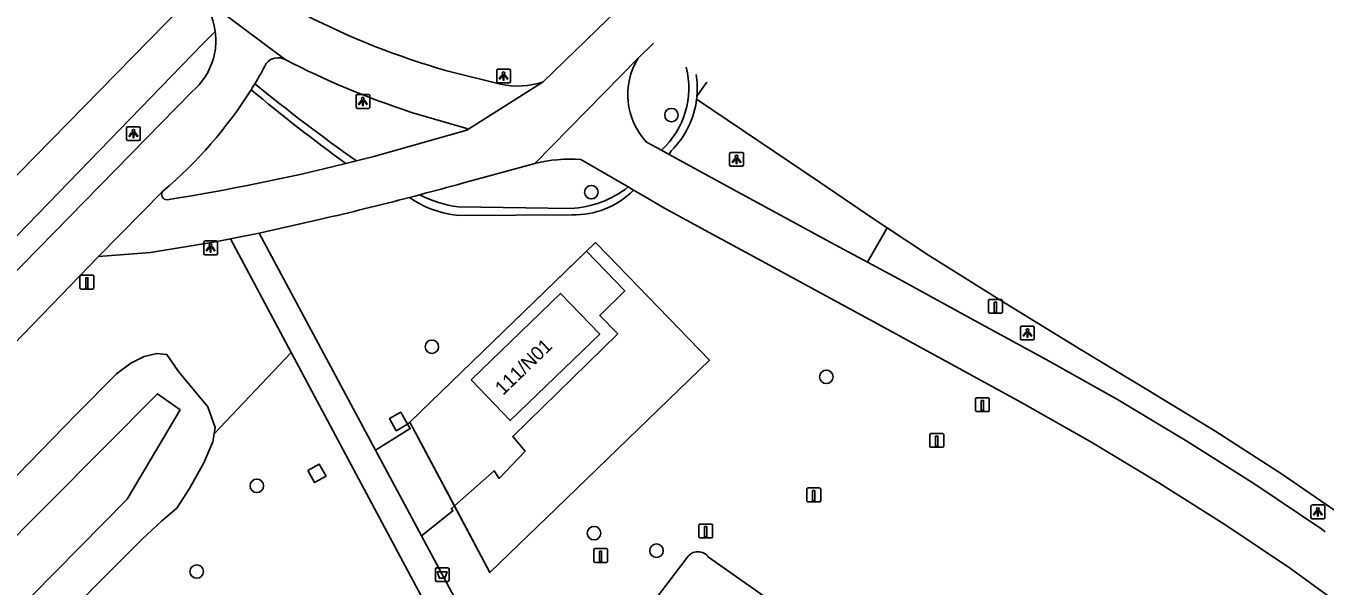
# Model space of a CAD drawing. Extents: x 155640 to 156810, y 382822 to 384046.
# Drawn here: x 156368.2 to 156462.3, y 383285.4 to 383326 of the extents above; entities that cross this region are included whole.
import ezdxf

# ---------------------------------------------------------------- set-up
doc = ezdxf.new("R2010")
doc.units = 0
for name, color, linetype in [('IMGEO_Afvalbak', 7, 'Continuous'), ('IMGEO_Berm_groen', 7, 'Continuous'), ('IMGEO_Boom', 7, 'Continuous'), ('IMGEO_Fietspad_gesloten', 7, 'Continuous'), ('IMGEO_Groenvoorziening', 7, 'Continuous'), ('IMGEO_Haag', 7, 'Continuous'), ('IMGEO_Hek', 7, 'Continuous'), ('IMGEO_Lichtpunt', 7, 'Continuous'), ('IMGEO_Muur', 7, 'Continuous'), ('IMGEO_Paal', 7, 'Continuous'), ('IMGEO_Pand', 7, 'Continuous'), ('IMGEO_Pand_nummerreeks', 7, 'Continuous'), ('IMGEO_Verkeerseiland_open', 7, 'Continuous'), ('IMGEO_Voetpad_gesloten', 7, 'Continuous'), ('IMGEO_Voetpad_onverhard', 7, 'Continuous'), ('IMGEO_Voetpad_open', 7, 'Continuous'), ('IMGEO_Waterloop', 7, 'Continuous')]:
    doc.layers.add(name, color=color, linetype=linetype)

msp = doc.modelspace()

# ---------------------------------------------------------------- linework, layer by layer
at = {"layer": 'IMGEO_Afvalbak'}
for p, q in [((156397.846, 383285.845), (156397.846, 383286.645)), ((156397.846, 383286.645), (156397.846, 383285.845)), ((156397.946, 383286.745), (156398.736, 383286.745)), ((156398.736, 383286.745), (156397.946, 383286.745)), ((156398.836, 383286.645), (156398.836, 383285.845)), ((156398.836, 383285.845), (156398.836, 383286.645)), ((156398.736, 383285.745), (156397.946, 383285.745)), ((156397.946, 383285.745), (156398.736, 383285.745))]:
    msp.add_line(p, q, dxfattribs=at)
msp.add_lwpolyline([(156397.989, 383286.459), (156398.693, 383286.459), (156398.544, 383285.989), (156398.138, 383285.989), (156397.989, 383286.459)], dxfattribs=at)
for centre, start, end in [((156397.946, 383286.645), 90, 180), ((156397.946, 383286.645), 90, 180), ((156398.736, 383286.645), 0, 90), ((156398.736, 383286.645), 360, 90), ((156397.946, 383285.845), 180, 270), ((156397.946, 383285.845), 180, 270), ((156398.736, 383285.845), 270, 0), ((156398.736, 383285.845), 270, 0)]:
    msp.add_arc(centre, 0.1, start, end, dxfattribs=at)
at = {"layer": 'IMGEO_Berm_groen'}
for points in [[(156387.41, 383302.346), (156383.014, 383310.578)], [(156233.027, 383113.173), (156252.866, 383146.34), (156268.602, 383172.647), (156299.809, 383224.819), (156307.157, 383232.786), (156316.472, 383242.07), (156333.801, 383259.79), (156347.065, 383272.962), (156352.588, 383278.703), (156361.434, 383287.344), (156366.724, 383292.604), (156371.834, 383297.853), (156374.748, 383300.784), (156375.78, 383301.56), (156376.759, 383302.039), (156377.674, 383302.264), (156378.399, 383302.193), (156379.248, 383300.961), (156381.369, 383298.415), (156381.897, 383296.903), (156381.815, 383296.443)], [(156387.41, 383302.346), (156381.815, 383296.443)]]:
    msp.add_lwpolyline(points, dxfattribs=at)
at = {"layer": 'IMGEO_Boom'}
for centre in [(156414.951, 383319.535), (156409.148, 383313.953), (156397.595, 383302.756), (156426.175, 383300.58), (156384.909, 383292.681), (156409.344, 383289.257), (156413.866, 383287.982), (156380.557, 383286.474)]:
    msp.add_circle(centre, 0.489, dxfattribs=at)
at = {"layer": 'IMGEO_Fietspad_gesloten'}
for points in [[(156386.96, 383323.552), (156380.504, 383328.406)], [(156411.874, 383327.981), (156405.667, 383321.95)], [(156413.66, 383324.737), (156412.539, 383323.648)], [(156405.049, 383316.037), (156412.539, 383323.648)], [(156402.557, 383321.777), (156398.667, 383322.745)], [(156405.667, 383321.95), (156400.124, 383318.442)], [(156380.194, 383321.217), (156360.181, 383300.803), (156343.328, 383283.312), (156320.142, 383258.454)], [(156384.5, 383321.375), (156384.634, 383321.592), (156384.768, 383321.81)], [(156396.11, 383319.733), (156400.129, 383318.562), (156400.124, 383318.442)], [(156400.124, 383318.442), (156393.394, 383316.534), (156392.135, 383316.212)], [(156413.154, 383317.575), (156414.222, 383316.991)], [(156392.135, 383316.212), (156391.748, 383316.116), (156391.361, 383316.02)], [(156408.386, 383316.322), (156411.813, 383314.329)], [(156414.222, 383316.991), (156414.359, 383316.916), (156414.78, 383316.686)], [(156414.78, 383316.686), (156419.216, 383314.26), (156426.506, 383310.311), (156429.166, 383308.873)], [(156399.819, 383314.599), (156405.049, 383316.037)], [(156411.813, 383314.329), (156412.207, 383314.099)], [(156373.432, 383309.293), (156378.108, 383314.02)], [(156395.984, 383313.573), (156396.356, 383313.67), (156396.729, 383313.767)], [(156469.029, 383279.65), (156464.349, 383283.389), (156459.799, 383286.696), (156455.125, 383289.825), (156450.27, 383292.91), (156445.339, 383295.87), (156440.217, 383298.767), (156435.055, 383301.593), (156429.889, 383304.414), (156427.301, 383305.816), (156421.201, 383309.128), (156417.685, 383311.033), (156414.393, 383312.827), (156412.93, 383313.678), (156412.207, 383314.099)], [(156385.084, 383310.986), (156389.538, 383311.991)], [(156383.014, 383310.578), (156381.78, 383310.334), (156377.211, 383309.584), (156373.432, 383309.293)], [(156383.014, 383310.578), (156385.084, 383310.986)], [(156373.432, 383309.293), (156346.778, 383281.729), (156322.635, 383255.833)], [(156462.324, 383289.355), (156462.066, 383289.543), (156457.215, 383292.799), (156452.282, 383295.927), (156447.27, 383298.926), (156442.11, 383301.833), (156436.911, 383304.669), (156431.712, 383307.496), (156429.166, 383308.873)]]:
    msp.add_lwpolyline(points, dxfattribs=at)
for centre, radius, start, end in [((156377.296, 383325.073), 4.626, 6.52779, 46.09498), ((156414.327, 383377.419), 56.872, 242.94269, 254.01676), ((156377.156, 383324.92), 4.785, 353.42613, 8.16143), ((156377.193, 383324.912), 4.747, 344.44891, 353.47288), ((156377.133, 383324.925), 4.808, 309.53884, 344.48996), ((156362.021, 383335.7), 26.653, 328.59089, 332.19886), ((156386.438, 383322.641), 1.05, 60.19021, 143.26914), ((156415.713, 383379.57), 62.966, 242.82975, 251.86117), ((156416.776, 383321.009), 4.992, 148.08972, 223.4753), ((156403.809, 383327.314), 5.676, 257.25954, 289.10828), ((156357.442, 383338.435), 31.988, 310.24597, 327.76827), ((156407.66, 383305.149), 11.196, 86.27976, 103.48336), ((156353.48, 383470.12), 158.687, 279.04397, 283.81086), ((156332.865, 383557.107), 251.581, 284.70542, 285.43422), ((156378.385, 383313.773), 0.371, 138.27225, 276.11786), ((156334.578, 383549.852), 244.128, 283.01029, 284.56809)]:
    msp.add_arc(centre, radius, start, end, dxfattribs=at)
at = {"layer": 'IMGEO_Groenvoorziening'}
for points in [[(156385.084, 383310.986), (156393.506, 383295.268)], [(156408.79, 383309.671), (156409.44, 383310.3), (156410.313, 383309.402), (156417.72, 383301.78), (156406.599, 383291.031), (156401.804, 383286.397), (156399.225, 383291.239)], [(156401.917, 383275.179), (156387.41, 383302.346)], [(156381.815, 383296.443), (156381.713, 383295.875), (156381.067, 383294.349), (156380.037, 383292.488), (156379.109, 383291.061), (156378.013, 383290.134), (156376.603, 383288.823), (156373.814, 383286.022), (156313.066, 383224.543), (156307.199, 383217.739), (156241.776, 383106.748)], [(156396.831, 383289.064), (156404.514, 383274.725)], [(156391.304, 383256.05), (156399.967, 383266.294), (156405.916, 383274.122), (156416.081, 383287.497)], [(156417.644, 383287.515), (156464.717, 383254.463), (156470.772, 383249.999), (156500, 383228.451), (156512.747, 383219.053)]]:
    msp.add_lwpolyline(points, dxfattribs=at)
msp.add_arc((156416.869, 383286.945), 0.962, 36.33381, 144.9858, dxfattribs=at)
at = {"layer": 'IMGEO_Haag'}
for points in [[(156414.78, 383316.686), (156414.939, 383316.944)], [(156429.166, 383308.873), (156430.583, 383311.361)]]:
    msp.add_lwpolyline(points, dxfattribs=at)
msp.add_arc((156410.444, 383321.475), 6.382, 314.77376, 352.81071, dxfattribs=at)
at = {"layer": 'IMGEO_Hek'}
for points in [[(156396, 383297.293), (156409.44, 383310.3)], [(156409.44, 383310.3), (156410.313, 383309.402)], [(156410.313, 383309.402), (156417.72, 383301.78), (156406.599, 383291.031)], [(156396, 383297.293), (156401.804, 383286.397)], [(156406.599, 383291.031), (156401.804, 383286.397)]]:
    msp.add_lwpolyline(points, dxfattribs=at)
at = {"layer": 'IMGEO_Lichtpunt'}
for p, q in [((156402.29, 383322.763), (156402.29, 383321.956)), ((156402.29, 383322.763), (156402.29, 383321.956)), ((156403.192, 383322.858), (156402.384, 383322.858)), ((156403.192, 383322.858), (156402.384, 383322.858)), ((156403.286, 383321.956), (156403.286, 383322.763)), ((156403.286, 383321.956), (156403.286, 383322.763)), ((156402.384, 383321.862), (156403.192, 383321.862)), ((156402.384, 383321.862), (156403.192, 383321.862)), ((156392.102, 383320.925), (156392.102, 383320.118)), ((156392.102, 383320.925), (156392.102, 383320.118)), ((156393.004, 383321.02), (156392.196, 383321.02)), ((156393.004, 383321.02), (156392.196, 383321.02)), ((156393.098, 383320.118), (156393.098, 383320.925)), ((156393.098, 383320.118), (156393.098, 383320.925)), ((156392.196, 383320.024), (156393.004, 383320.024)), ((156392.196, 383320.024), (156393.004, 383320.024)), ((156375.469, 383318.599), (156375.469, 383317.792)), ((156375.469, 383318.599), (156375.469, 383317.792)), ((156376.371, 383318.694), (156375.563, 383318.694)), ((156376.371, 383318.694), (156375.563, 383318.694)), ((156376.465, 383317.792), (156376.465, 383318.599)), ((156376.465, 383317.792), (156376.465, 383318.599)), ((156375.563, 383317.698), (156376.371, 383317.698)), ((156375.563, 383317.698), (156376.371, 383317.698)), ((156419.169, 383316.73), (156419.169, 383315.923)), ((156419.169, 383316.73), (156419.169, 383315.923)), ((156420.071, 383316.825), (156419.263, 383316.825)), ((156420.071, 383316.825), (156419.263, 383316.825)), ((156420.165, 383315.923), (156420.165, 383316.73)), ((156420.165, 383315.923), (156420.165, 383316.73)), ((156419.263, 383315.829), (156420.071, 383315.829)), ((156419.263, 383315.829), (156420.071, 383315.829)), ((156381.064, 383310.322), (156381.064, 383309.515)), ((156381.064, 383310.322), (156381.064, 383309.515)), ((156381.966, 383310.417), (156381.158, 383310.417)), ((156381.966, 383310.417), (156381.158, 383310.417)), ((156382.06, 383309.515), (156382.06, 383310.322)), ((156382.06, 383309.515), (156382.06, 383310.322)), ((156381.158, 383309.421), (156381.966, 383309.421)), ((156381.158, 383309.421), (156381.966, 383309.421)), ((156440.244, 383304.152), (156440.244, 383303.345)), ((156440.244, 383304.152), (156440.244, 383303.345)), ((156441.146, 383304.247), (156440.338, 383304.247)), ((156441.146, 383304.247), (156440.338, 383304.247)), ((156441.24, 383303.345), (156441.24, 383304.152)), ((156441.24, 383303.345), (156441.24, 383304.152)), ((156440.338, 383303.251), (156441.146, 383303.251)), ((156440.338, 383303.251), (156441.146, 383303.251)), ((156461.288, 383291.201), (156461.288, 383290.394)), ((156461.288, 383291.201), (156461.288, 383290.394)), ((156462.19, 383291.296), (156461.382, 383291.296)), ((156462.19, 383291.296), (156461.382, 383291.296)), ((156462.284, 383290.394), (156462.284, 383291.201)), ((156462.284, 383290.394), (156462.284, 383291.201)), ((156461.382, 383290.3), (156462.19, 383290.3)), ((156461.382, 383290.3), (156462.19, 383290.3))]:
    msp.add_line(p, q, dxfattribs=at)
for points in [[(156402.664, 383322.427), (156402.703, 383322.399), (156402.515, 383322.137), (156402.477, 383322.164), (156402.664, 383322.427)], [(156402.766, 383322.379), (156402.813, 383322.379), (156402.813, 383322.057), (156402.766, 383322.057), (156402.766, 383322.379)], [(156402.876, 383322.399), (156402.914, 383322.426), (156403.101, 383322.164), (156403.062, 383322.136), (156402.876, 383322.399)], [(156392.476, 383320.589), (156392.515, 383320.561), (156392.327, 383320.299), (156392.289, 383320.326), (156392.476, 383320.589)], [(156392.578, 383320.541), (156392.625, 383320.541), (156392.625, 383320.219), (156392.578, 383320.219), (156392.578, 383320.541)], [(156392.688, 383320.561), (156392.726, 383320.588), (156392.913, 383320.326), (156392.874, 383320.298), (156392.688, 383320.561)], [(156375.843, 383318.263), (156375.882, 383318.235), (156375.694, 383317.973), (156375.656, 383318), (156375.843, 383318.263)], [(156375.945, 383318.215), (156375.992, 383318.215), (156375.992, 383317.893), (156375.945, 383317.893), (156375.945, 383318.215)], [(156376.055, 383318.235), (156376.093, 383318.262), (156376.28, 383318), (156376.241, 383317.972), (156376.055, 383318.235)], [(156419.543, 383316.394), (156419.582, 383316.366), (156419.394, 383316.104), (156419.356, 383316.131), (156419.543, 383316.394)], [(156419.645, 383316.346), (156419.692, 383316.346), (156419.692, 383316.024), (156419.645, 383316.024), (156419.645, 383316.346)], [(156419.755, 383316.366), (156419.793, 383316.393), (156419.98, 383316.131), (156419.941, 383316.103), (156419.755, 383316.366)], [(156381.438, 383309.986), (156381.477, 383309.958), (156381.289, 383309.696), (156381.251, 383309.723), (156381.438, 383309.986)], [(156381.54, 383309.938), (156381.587, 383309.938), (156381.587, 383309.616), (156381.54, 383309.616), (156381.54, 383309.938)], [(156381.65, 383309.958), (156381.688, 383309.985), (156381.875, 383309.723), (156381.836, 383309.695), (156381.65, 383309.958)], [(156440.618, 383303.816), (156440.657, 383303.788), (156440.469, 383303.526), (156440.431, 383303.553), (156440.618, 383303.816)], [(156440.72, 383303.768), (156440.767, 383303.768), (156440.767, 383303.446), (156440.72, 383303.446), (156440.72, 383303.768)], [(156440.83, 383303.788), (156440.868, 383303.815), (156441.055, 383303.553), (156441.016, 383303.525), (156440.83, 383303.788)], [(156461.662, 383290.865), (156461.701, 383290.837), (156461.513, 383290.575), (156461.475, 383290.602), (156461.662, 383290.865)], [(156461.764, 383290.817), (156461.811, 383290.817), (156461.811, 383290.495), (156461.764, 383290.495), (156461.764, 383290.817)], [(156461.874, 383290.837), (156461.912, 383290.864), (156462.099, 383290.602), (156462.06, 383290.574), (156461.874, 383290.837)]]:
    msp.add_lwpolyline(points, dxfattribs=at)
for centre in [(156402.789, 383322.561), (156392.601, 383320.723), (156375.968, 383318.397), (156419.668, 383316.528), (156381.563, 383310.12), (156440.743, 383303.95), (156461.787, 383290.999)]:
    msp.add_circle(centre, 0.0994, dxfattribs=at)
for centre, start, end in [((156402.384, 383322.763), 90, 180), ((156402.384, 383322.763), 90, 180), ((156403.192, 383322.763), 0, 90), ((156403.192, 383322.763), 0, 90), ((156402.384, 383321.956), 180, 270), ((156402.384, 383321.956), 180, 270), ((156403.192, 383321.956), 270, 0), ((156403.192, 383321.956), 270, 360), ((156392.196, 383320.925), 90, 180), ((156392.196, 383320.925), 90, 180), ((156393.004, 383320.925), 0, 90), ((156393.004, 383320.925), 0, 90), ((156392.196, 383320.118), 180, 270), ((156392.196, 383320.118), 180, 270), ((156393.004, 383320.118), 270, 0), ((156393.004, 383320.118), 270, 360), ((156375.563, 383318.599), 90, 180), ((156375.563, 383318.599), 90, 180), ((156376.371, 383318.599), 0, 90), ((156376.371, 383318.599), 0, 90), ((156375.563, 383317.792), 180, 270), ((156375.563, 383317.792), 180, 270), ((156376.371, 383317.792), 270, 0), ((156376.371, 383317.792), 270, 360), ((156419.263, 383316.73), 90, 180), ((156419.263, 383316.73), 90, 180), ((156420.071, 383316.73), 0, 90), ((156420.071, 383316.73), 0, 90), ((156419.263, 383315.923), 180, 270), ((156419.263, 383315.923), 180, 270), ((156420.071, 383315.923), 270, 0), ((156420.071, 383315.923), 270, 360), ((156381.158, 383310.322), 90, 180), ((156381.158, 383310.322), 90, 180), ((156381.966, 383310.322), 0, 90), ((156381.966, 383310.322), 0, 90), ((156381.158, 383309.515), 180, 270), ((156381.158, 383309.515), 180, 270), ((156381.966, 383309.515), 270, 0), ((156381.966, 383309.515), 270, 360), ((156440.338, 383304.152), 90, 180), ((156440.338, 383304.152), 90, 180), ((156441.146, 383304.152), 0, 90), ((156441.146, 383304.152), 0, 90), ((156440.338, 383303.345), 180, 270), ((156440.338, 383303.345), 180, 270), ((156441.146, 383303.345), 270, 0), ((156441.146, 383303.345), 270, 360), ((156461.382, 383291.201), 90, 180), ((156461.382, 383291.201), 90, 180), ((156462.19, 383291.201), 0, 90), ((156462.19, 383291.201), 0, 90), ((156461.382, 383290.394), 180, 270), ((156461.382, 383290.394), 180, 270), ((156462.19, 383290.394), 270, 0), ((156462.19, 383290.394), 270, 360)]:
    msp.add_arc(centre, 0.0946, start, end, dxfattribs=at)
at = {"layer": 'IMGEO_Muur'}
for points in [[(156395.84, 383297.138), (156395.016, 383296.673), (156394.52, 383297.548), (156395.342, 383298.015), (156395.84, 383297.138)], [(156388.605, 383293.791), (156389.427, 383294.258), (156389.924, 383293.383), (156389.101, 383292.916), (156388.605, 383293.791)]]:
    msp.add_lwpolyline(points, dxfattribs=at)
at = {"layer": 'IMGEO_Paal'}
for p, q in [((156372.099, 383307.854), (156372.099, 383307.013)), ((156372.099, 383307.854), (156372.099, 383307.013)), ((156373.015, 383307.938), (156372.174, 383307.938)), ((156373.015, 383307.938), (156372.174, 383307.938)), ((156373.099, 383307.022), (156373.099, 383307.863)), ((156373.099, 383307.022), (156373.099, 383307.863)), ((156372.183, 383306.938), (156373.024, 383306.938)), ((156372.183, 383306.938), (156373.024, 383306.938)), ((156437.927, 383306.098), (156437.927, 383305.257)), ((156437.927, 383306.098), (156437.927, 383305.257)), ((156438.843, 383306.182), (156438.002, 383306.182)), ((156438.843, 383306.182), (156438.002, 383306.182)), ((156438.927, 383305.266), (156438.927, 383306.107)), ((156438.927, 383305.266), (156438.927, 383306.107)), ((156438.011, 383305.182), (156438.852, 383305.182)), ((156438.011, 383305.182), (156438.852, 383305.182)), ((156436.98, 383298.976), (156436.98, 383298.135)), ((156436.98, 383298.976), (156436.98, 383298.135)), ((156437.896, 383299.06), (156437.055, 383299.06)), ((156437.896, 383299.06), (156437.055, 383299.06)), ((156437.98, 383298.144), (156437.98, 383298.985)), ((156437.98, 383298.144), (156437.98, 383298.985)), ((156437.064, 383298.06), (156437.905, 383298.06)), ((156437.064, 383298.06), (156437.905, 383298.06)), ((156434.591, 383296.475), (156433.75, 383296.475)), ((156434.591, 383296.475), (156433.75, 383296.475)), ((156433.675, 383296.391), (156433.675, 383295.55)), ((156433.675, 383296.391), (156433.675, 383295.55)), ((156433.759, 383295.475), (156434.6, 383295.475)), ((156433.759, 383295.475), (156434.6, 383295.475)), ((156434.675, 383295.559), (156434.675, 383296.4)), ((156434.675, 383295.559), (156434.675, 383296.4)), ((156424.763, 383292.443), (156424.763, 383291.602)), ((156424.763, 383292.443), (156424.763, 383291.602)), ((156425.679, 383292.527), (156424.838, 383292.527)), ((156425.679, 383292.527), (156424.838, 383292.527)), ((156425.763, 383291.611), (156425.763, 383292.452)), ((156425.763, 383291.611), (156425.763, 383292.452)), ((156424.847, 383291.527), (156425.688, 383291.527)), ((156424.847, 383291.527), (156425.688, 383291.527)), ((156416.935, 383289.833), (156416.935, 383288.992)), ((156416.935, 383289.833), (156416.935, 383288.992)), ((156417.851, 383289.917), (156417.01, 383289.917)), ((156417.851, 383289.917), (156417.01, 383289.917)), ((156417.935, 383289.001), (156417.935, 383289.842)), ((156417.935, 383289.001), (156417.935, 383289.842)), ((156417.019, 383288.917), (156417.86, 383288.917)), ((156417.019, 383288.917), (156417.86, 383288.917)), ((156409.319, 383288.05), (156409.319, 383287.209)), ((156409.319, 383288.05), (156409.319, 383287.209)), ((156410.235, 383288.134), (156409.394, 383288.134)), ((156410.235, 383288.134), (156409.394, 383288.134)), ((156410.319, 383287.218), (156410.319, 383288.059)), ((156410.319, 383287.218), (156410.319, 383288.059)), ((156409.403, 383287.134), (156410.244, 383287.134)), ((156409.403, 383287.134), (156410.244, 383287.134))]:
    msp.add_line(p, q, dxfattribs=at)
for points in [[(156372.514, 383307.751), (156372.674, 383307.751), (156372.674, 383307.018), (156372.514, 383307.018), (156372.514, 383307.751)], [(156438.342, 383305.995), (156438.502, 383305.995), (156438.502, 383305.262), (156438.342, 383305.262), (156438.342, 383305.995)], [(156437.395, 383298.873), (156437.555, 383298.873), (156437.555, 383298.14), (156437.395, 383298.14), (156437.395, 383298.873)], [(156434.09, 383296.288), (156434.25, 383296.288), (156434.25, 383295.555), (156434.09, 383295.555), (156434.09, 383296.288)], [(156425.178, 383292.34), (156425.338, 383292.34), (156425.338, 383291.607), (156425.178, 383291.607), (156425.178, 383292.34)], [(156417.35, 383289.73), (156417.51, 383289.73), (156417.51, 383288.997), (156417.35, 383288.997), (156417.35, 383289.73)], [(156409.734, 383287.947), (156409.894, 383287.947), (156409.894, 383287.214), (156409.734, 383287.214), (156409.734, 383287.947)]]:
    msp.add_lwpolyline(points, dxfattribs=at)
for centre, start, end in [((156372.177, 383307.86), 92.4484, 184.28452), ((156372.177, 383307.86), 92.4484, 184.28452), ((156373.021, 383307.86), 2.4484, 94.28452), ((156373.021, 383307.86), 2.4484, 94.28452), ((156372.177, 383307.016), 182.4484, 274.28452), ((156372.177, 383307.016), 182.4484, 274.28452), ((156373.021, 383307.016), 272.4484, 4.28452), ((156373.021, 383307.016), 272.4484, 4.28452), ((156438.005, 383306.104), 92.4484, 184.28452), ((156438.005, 383306.104), 92.4484, 184.28452), ((156438.849, 383306.104), 2.4484, 94.28452), ((156438.849, 383306.104), 2.4484, 94.28452), ((156438.005, 383305.26), 182.4484, 274.28452), ((156438.005, 383305.26), 182.4484, 274.28452), ((156438.849, 383305.26), 272.4484, 4.28452), ((156438.849, 383305.26), 272.4484, 4.28452), ((156437.058, 383298.982), 92.4484, 184.28452), ((156437.058, 383298.982), 92.4484, 184.28452), ((156437.902, 383298.982), 2.4484, 94.28452), ((156437.902, 383298.982), 2.4484, 94.28452), ((156437.058, 383298.138), 182.4484, 274.28452), ((156437.058, 383298.138), 182.4484, 274.28452), ((156437.902, 383298.138), 272.4484, 4.28452), ((156437.902, 383298.138), 272.4484, 4.28452), ((156433.753, 383296.397), 92.4484, 184.28452), ((156433.753, 383296.397), 92.4484, 184.28452), ((156434.597, 383296.397), 2.4484, 94.28452), ((156434.597, 383296.397), 2.4484, 94.28452), ((156433.753, 383295.553), 182.4484, 274.28452), ((156433.753, 383295.553), 182.4484, 274.28452), ((156434.597, 383295.553), 272.4484, 4.28452), ((156434.597, 383295.553), 272.4484, 4.28452), ((156424.841, 383292.449), 92.4484, 184.28452), ((156424.841, 383292.449), 92.4484, 184.28452), ((156425.685, 383292.449), 2.4484, 94.28452), ((156425.685, 383292.449), 2.4484, 94.28452), ((156424.841, 383291.605), 182.4484, 274.28452), ((156424.841, 383291.605), 182.4484, 274.28452), ((156425.685, 383291.605), 272.4484, 4.28452), ((156425.685, 383291.605), 272.4484, 4.28452), ((156417.013, 383289.839), 92.4484, 184.28452), ((156417.013, 383289.839), 92.4484, 184.28452), ((156417.857, 383289.839), 2.4484, 94.28452), ((156417.857, 383289.839), 2.4484, 94.28452), ((156417.013, 383288.995), 182.4484, 274.28452), ((156417.013, 383288.995), 182.4484, 274.28452), ((156417.857, 383288.995), 272.4484, 4.28452), ((156417.857, 383288.995), 272.4484, 4.28452), ((156409.397, 383288.056), 92.4484, 184.28452), ((156409.397, 383288.056), 92.4484, 184.28452), ((156410.241, 383288.056), 2.4484, 94.28452), ((156410.241, 383288.056), 2.4484, 94.28452), ((156409.397, 383287.212), 182.4484, 274.28452), ((156409.397, 383287.212), 182.4484, 274.28452), ((156410.241, 383287.212), 272.4484, 4.28452), ((156410.241, 383287.212), 272.4484, 4.28452)]:
    msp.add_arc(centre, 0.0779, start, end, dxfattribs=at)
at = {"layer": 'IMGEO_Pand'}
msp.add_lwpolyline([(156400.449, 383300.359), (156406.909, 383306.619), (156409.756, 383303.668), (156403.272, 383297.412), (156400.449, 383300.359)], dxfattribs=at)
at = {"layer": 'IMGEO_Verkeerseiland_open'}
for points in [[(156399.51, 383312.894), (156407.664, 383312.773)], [(156407.731, 383312.309), (156399.621, 383312.271)]]:
    msp.add_lwpolyline(points, dxfattribs=at)
for centre, radius, start, end in [((156410.097, 383321.498), 6.11, 312.46936, 14.33577), ((156465.056, 383417.513), 125.426, 230.03972, 234.01632), ((156465.596, 383420.533), 127.591, 230.69177, 234.84764), ((156407.309, 383320.03), 7.266, 272.804, 308.31112), ((156400.077, 383319.277), 7.021, 234.33453, 266.27202), ((156400.443, 383320.733), 7.895, 241.93421, 263.20999), ((156407.902, 383318.372), 6.065, 268.38031, 315.21368)]:
    msp.add_arc(centre, radius, start, end, dxfattribs=at)
at = {"layer": 'IMGEO_Voetpad_gesloten'}
for points in [[(156380.504, 383328.406), (156380.013, 383327.906), (156379.48, 383327.364), (156361.745, 383309.309), (156335.323, 383281.619), (156308.935, 383253.615)], [(156381.892, 383325.599), (156381.348, 383325.039), (156380.959, 383324.639), (156363.82, 383307.004), (156337.443, 383279.37), (156311.15, 383251.521)], [(156417.508, 383321.917), (156416.801, 383320.912)], [(156416.776, 383320.676), (156416.789, 383320.794), (156416.801, 383320.912)], [(156416.776, 383320.676), (156425.73, 383314.654), (156429.668, 383311.964), (156430.583, 383311.361)], [(156430.583, 383311.361), (156433.651, 383309.341), (156439.121, 383305.912), (156444.63, 383302.545), (156449.523, 383299.599), (156454.393, 383296.613), (156459.141, 383293.542), (156463.241, 383290.742)]]:
    msp.add_lwpolyline(points, dxfattribs=at)
at = {"layer": 'IMGEO_Voetpad_onverhard'}
msp.add_arc((156410.444, 383321.472), 6.382, 354.96469, 9.04836, dxfattribs=at)
at = {"layer": 'IMGEO_Voetpad_open'}
for points in [[(156396, 383297.293), (156408.79, 383309.671)], [(156399.225, 383291.239), (156402.105, 383293.774), (156402.473, 383293.222), (156404.345, 383295.185), (156403.455, 383296.258), (156411.064, 383303.686), (156409.755, 383305.026), (156411.57, 383306.798), (156408.79, 383309.671)], [(156393.506, 383295.268), (156396.023, 383296.828), (156395.84, 383297.138)], [(156395.84, 383297.138), (156396, 383297.293)], [(156396, 383297.293), (156399.225, 383291.239)], [(156393.506, 383295.268), (156396.831, 383289.064)], [(156399.225, 383291.239), (156399.005, 383291.045), (156399.107, 383290.866), (156396.831, 383289.064)]]:
    msp.add_lwpolyline(points, dxfattribs=at)
at = {"layer": 'IMGEO_Waterloop'}
msp.add_lwpolyline([(156309.837, 383225.147), (156375.527, 383291.728), (156379.347, 383298.182), (156377.724, 383299.338), (156314.169, 383235.475)], dxfattribs=at)

# ---------------------------------------------------------------- texts
at = {"layer": 'IMGEO_Pand_nummerreeks'}
msp.add_text('111/N01', height=1, rotation=44.00727, dxfattribs=at).set_placement((156402.752, 383299.193))

doc.saveas('drawing.dxf')
